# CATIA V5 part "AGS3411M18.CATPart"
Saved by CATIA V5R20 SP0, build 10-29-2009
Part number: AGS3411M18
Definition: NONE
Nomenclature: AGS3411M18
Source: Unknown
Description: AGS3411M18
Bounding box of the stored display mesh (mm): x -35 to 33, y -17.347 to 17.347, z -14 to 14
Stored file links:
  C:\Users\Utente\Desktop\IO LAVORO\3D X SITO CF\X SITO\PLASTICA\AGS\AGS3411M18.CATPart
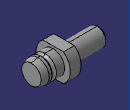
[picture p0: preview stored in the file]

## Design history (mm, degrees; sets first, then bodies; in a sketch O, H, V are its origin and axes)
Body1 "AGS3411M18" (main body)
  Solid1: solid without history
